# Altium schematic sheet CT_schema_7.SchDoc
size 255 x 245 mm
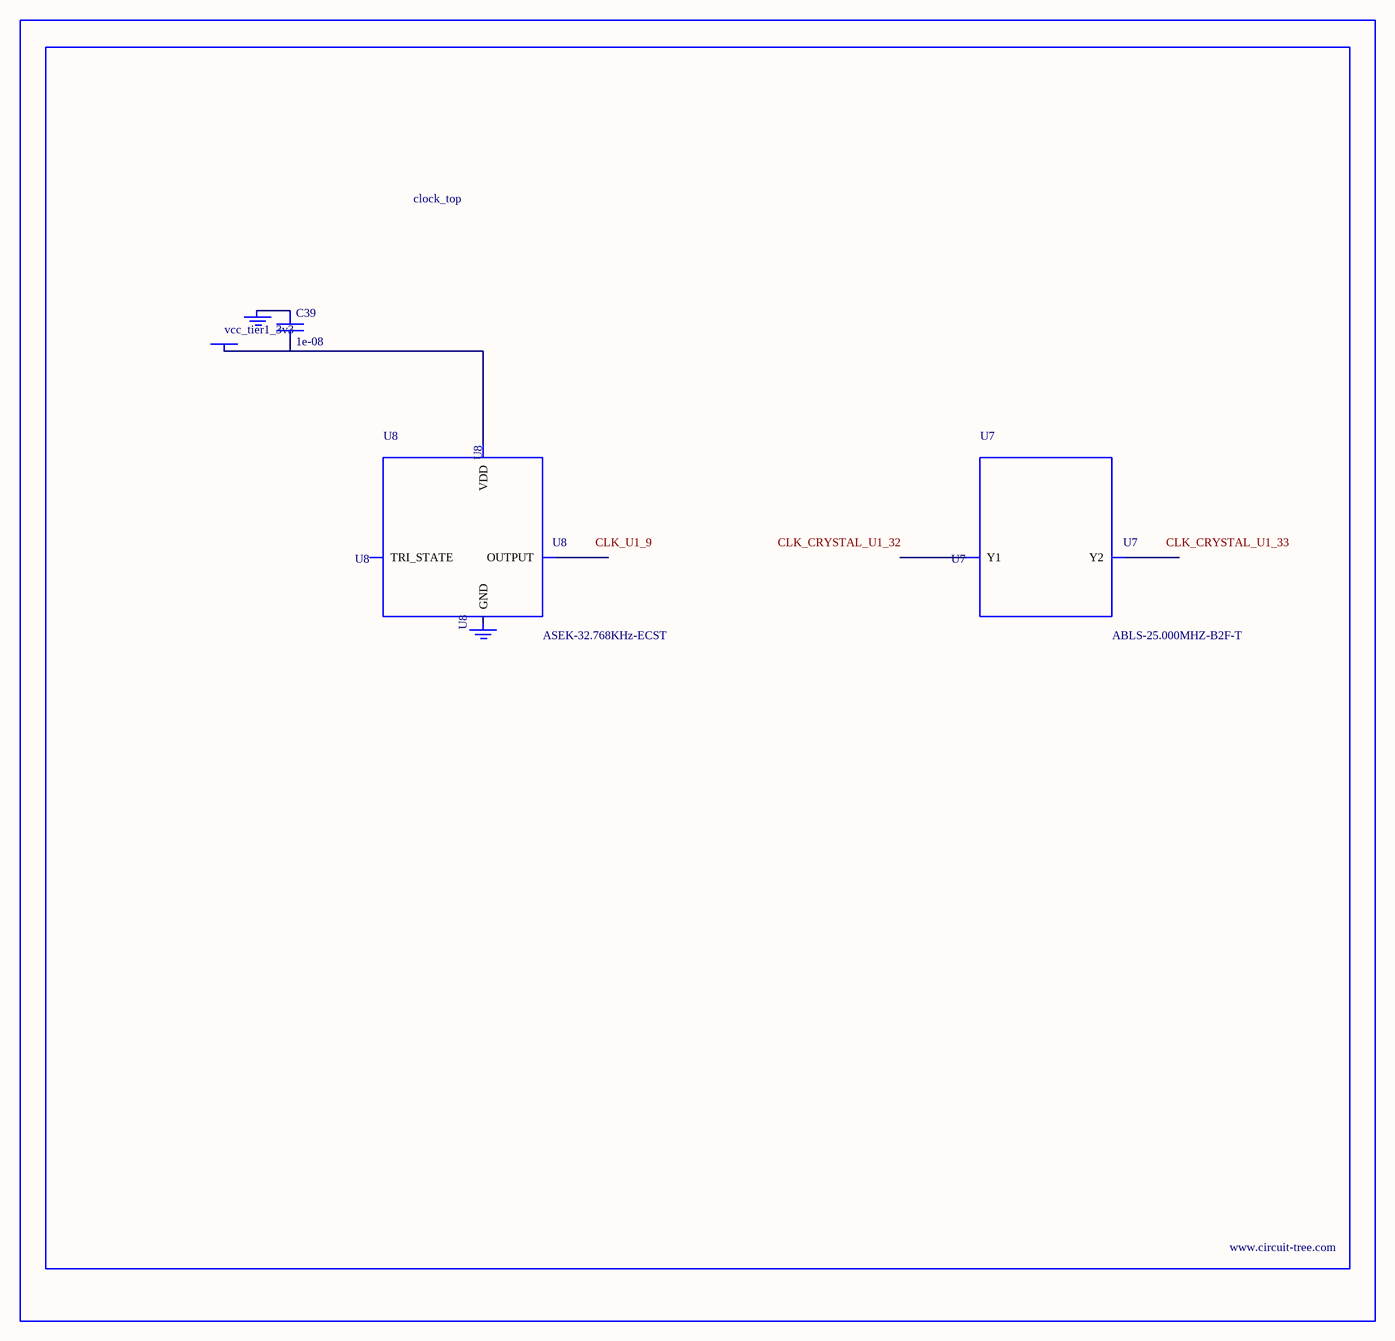
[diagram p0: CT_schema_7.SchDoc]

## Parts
BORDER6  (no value)
C39  1e-08  [C0402]
GND_INSTANCE_6_0  (no value)
GND_INSTANCE_6_1  (no value)
POWER_INSTANCE_6_0  vcc_tier1_3v3
U7  ABLS-25.000MHZ-B2F-T  [ABLS-25.000MHZ-B2F-T]
U8  ASEK-32.768KHz-ECST  [ASEK]

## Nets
NetC39_1: C39.1 GND_INSTANCE_6_0.0(GND)
NetC39_2: C39.2 POWER_INSTANCE_6_0.0(PWR) U8.4(VDD)

Not connected (* = marked no-connect by the designer): GND_INSTANCE_6_1 0(GND); U7 1(Y1) 2(Y2); U8 1(TRI_STATE) 2(GND) 3(OUTPUT)

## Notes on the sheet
- Labels drawn without touching a wire or pin: CLK_CRYSTAL_U1_32, CLK_CRYSTAL_U1_33, CLK_U1_9

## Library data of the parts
BORDER6 = BORDER_PAGE6
C39 = C0402C103K3RAC
GND_INSTANCE_6_0 GND_INSTANCE_6_1 = GND
POWER_INSTANCE_6_0 = PWR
